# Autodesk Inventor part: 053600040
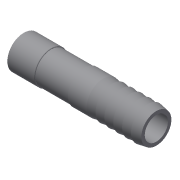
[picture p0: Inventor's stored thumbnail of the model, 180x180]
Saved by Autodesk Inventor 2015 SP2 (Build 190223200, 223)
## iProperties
Created: 2017-10
Part Number: 053600040
Material: Generic
Description: PLASSON HOSE NOZZLE-CEM. PVC 40
Document SubType Name: Modeling
Designer: KIM
Density: 1 g/cm^3
Appearance: Default
Author: KIM
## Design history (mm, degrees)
derived "053600.ipt"
feature "Solid1::053600.ipt"
tag "TaggingFeature1"
body "Solid1"
other parameters: "d0" = 95, "d1" = 170 deg, "d4" = 26, "d6" = 28, "d8" = 38, "d9" = 38.4, "d10" = 23.75, "d11" = 0.4, "d14" = 0.4, "H_" = 95, "L_" = 26
